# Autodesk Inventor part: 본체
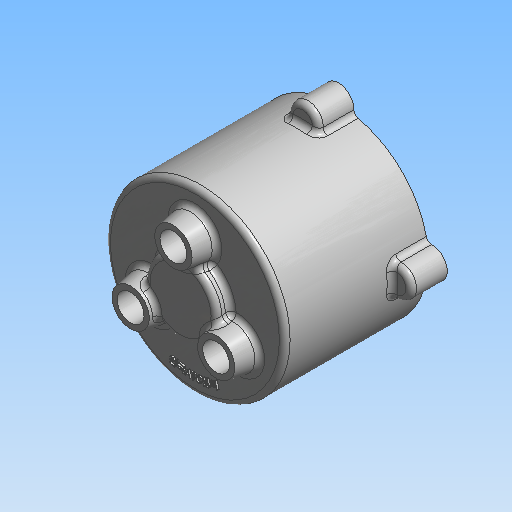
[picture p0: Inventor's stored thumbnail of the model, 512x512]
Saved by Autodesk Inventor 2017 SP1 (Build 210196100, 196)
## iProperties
Created: 2021-07
Part Number: 본체
Document SubType Name: 모델링
Designer: mdu
Material: 알루미늄 6061
Density: 2.71 g/cm^3
Appearance: 알루미늄 - 평지
Mass: 473.469 g
Surface Area: 688.944 cm^2
Volume: 174.712 cm^3
변환 표준: STEP AP214IS
파일 이름: C:\Users\SeoGD\Desktop\?쒗뿕\紐몄껜.stp
전처리기: Build: 253, Release: 2010 SP1 - Date: Wed 07/29/2009
전송 단위: 밀리미터
불확실성: 0.01
Author: mdu
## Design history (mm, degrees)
sketch "스케치2"
  geometry: C1 r 50 at (0, 0); 1 further point
  constraints: 1 centre point, 1 coincident
  dimensions: "d9" = 100 diameter of C1
extrude "돌출2" new body sketch "스케치2" distance "d10" = 80; taper "d11" = 0 deg
feature "쉘1" dims "d12" = 5
sketch "스케치3" dims "d13" = 55
  geometry: C1 r 7.5 at (0, 27.5); C2 r 12.5 at (0, 27.5); 2 further points
  constraints: 2 centre point, 2 coincident, 2 vertical alignment, 2 other
  dimensions: "d14" = 15 diameter of C1; "d15" = 25 diameter of C2
extrude "돌출3" join sketch "스케치3" distance "d16" = 12; taper "d17" = -10 deg
sketch "스케치4"
  geometry: L1 (0, 0)-(0, 88); L2 (0, 70)-(14, 70); L3 (-45, 75)-(45, 75) reference; L4 (-50, 80)-(50, 80) reference; L5 (14, 70)-(14, 75); L6 (20, 80)-(20, 88); L7 (20, 88)-(0, 88); L8 (20, 80)-(14, 75)
  constraints: 12 end point, 3 point on line, 2 perpendicular, 1 vertical
  dimensions: "d34" = 40 diameter of L6 L1; "d35" = 90 deg angle of L5 L3; "d36" = 5 distance between parallel lines of L2 L3; "d37" = 8 distance between parallel lines of L7 L4; "d51" = 28 diameter of L5.end L1
revolve "회전1" sketch "스케치4" stored, may be unused: angle "d38" = 90 deg
hole "구멍3" diameter "d41" = 15; stored, may be unused: countersink angle "d45" = 90 deg, drill point angle "d47" = 0 deg; dims "d39" = 10, "d40" = 10, "d42" = 6, "d43" = 22, "d44" = 13, "d46" = 15
chamfer "모따기2" distance "d48" = 1; stored, may be unused: second distance "d49" = 2, angle "d50" = 45 deg
fillet "모깎기4" dims "d78" = 3
hole "구멍2" diameter "d20" = 15; stored, may be unused: countersink angle "d24" = 90 deg, drill point angle "d26" = 118 deg; dims "d21" = 6, "d22" = 25, "d23" = 1, "d25" = 15, "d76" = 10, "d77" = 10
chamfer "모따기1" distance "d27" = 1; stored, may be unused: second distance "d28" = 2, angle "d29" = 45 deg
sketch "스케치9"
  geometry: C1 r 12.5 at (0, 0) reference; C2 r 12.5 at (-23.816, -41.25) reference; C3 r 12.5 at (23.816, -41.25) reference; 1 further point
extrude "돌출5" cut sketch "스케치9" stored distance "d79" = 10; taper "d80" = 0 deg
fillet "모깎기1" dims "d52" = 3
fillet "모깎기2" dims "d53" = 3, "d72" = 0.2
sketch "스케치5"
  geometry: A1 r 50 centre (0, 0) between (50, 0) and (-8.074, 49.344) reference; A2 r 8.5 centre (0, 52) between (8.074, 49.344) and (-8.074, 49.344); 1 further point
  constraints: 5 point on circle, 1 centre point, 1 horizontal alignment
  dimensions: "d54" = 90 deg dimension on point (0, 0) A2.centre A1.start; "d55" = 52 distance of A2.centre point (0, 0); "d56" = 17 diameter of A2
extrude "돌출4" join sketch "스케치5" distance "d57" = 20; taper "d58" = 0 deg
fillet "모깎기3" dims "d59" = 3
hole "구멍4" diameter "d62" = 4.134; stored, may be unused: countersink angle "d66" = 90 deg, drill point angle "d68" = 118 deg; dims "d60" = 10, "d61" = 10, "d63" = 12, "d64" = 22, "d65" = 13, "d67" = 15
sketch "스케치6"
  geometry: C1 r 47 at (0, 0) reference; C2 r 42.5 at (0, 0); 1 further point
  constraints: 1 centre point, 1 coincident, 1 other
  dimensions: "d73" = 85 diameter of C2
feature "엠보싱1" sketch "스케치6" dims "d34" = 40, "d35" = 90 deg, "d36" = 5, "d37" = 8, "d51" = 28, "d74" = 1, "d75" = 0
node "솔리드1"
node "솔리드 본체"
node "곡면 본체"
pattern_circular "원형 패턴1" dims angle "d31" = 360 deg
pattern_circular "원형 패턴2" dims angle "d70" = 360 deg
node "솔리드2"
